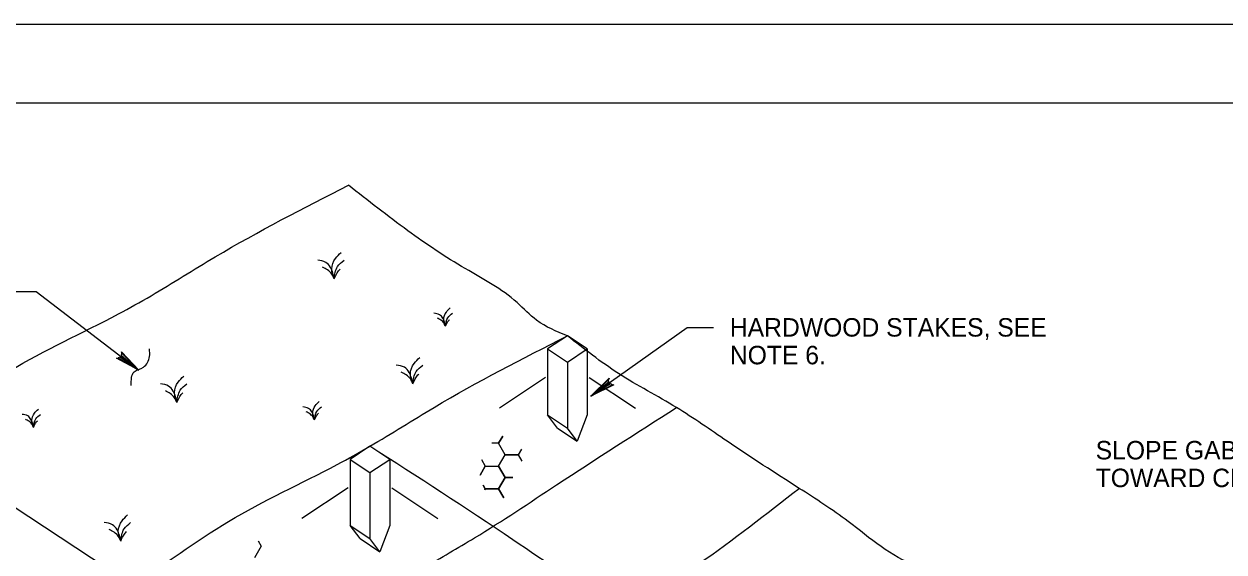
# Model space of a CAD drawing. Extents: x 3 to 3592, y -602 to 1171.
# Drawn here: x 3022.2 to 3249.7, y -107.8 to -7.8 of the extents above; entities that cross this region are included whole.
import ezdxf

# ---------------------------------------------------------------- set-up
doc = ezdxf.new("R2010")
doc.units = 0
for name, color, linetype in [('1', 7, 'Continuous'), ('2', 7, 'Continuous'), ('3', 7, 'Continuous')]:
    doc.layers.add(name, color=color, linetype=linetype)

msp = doc.modelspace()

# ---------------------------------------------------------------- linework, layer by layer
at = {"layer": '1'}
msp.add_lwpolyline([(2687.88, -7.81), (3528.88, -7.81), (3528.88, -601.81), (2687.88, -601.81)], close=True, dxfattribs=at)
msp.add_lwpolyline([(3512.88, -586.81), (3512.88, -22.81), (2726.88, -22.81), (2726.88, -586.81), (3512.88, -586.81), (3512.88, -560.45), (3312.88, -560.45), (3312.88, -495.77), (3512.88, -495.77), (3512.88, -466.81), (3312.88, -466.81), (3312.88, -586.81), (3391.68, -586.81), (3391.68, -560.45), (3391.68, -586.81), (3468.68, -586.81), (3468.68, -560.45), (3468.68, -572.77), (3512.88, -572.77)], dxfattribs=at)
at = {"layer": '2'}
for p, q in [((3121.47, -69.37), (3121.47, -81.87)), ((3128.97, -69.37), (3128.97, -81.87)), ((3128.97, -69.37), (3128.97, -69.37)), ((3125.22, -71.87), (3125.22, -84.37)), ((3121.08, -74.75), (3112.33, -80.58)), ((3128.97, -74.74), (3128.97, -74.74)), ((3129.36, -74.75), (3138.11, -80.58)), ((3121.47, -81.87), (3125.22, -84.37)), ((3123.35, -84.37), (3121.47, -81.87)), ((3128.97, -81.87), (3127.1, -86.87)), ((3123.35, -84.37), (3127.1, -86.87)), ((3127.1, -86.87), (3125.22, -84.37)), ((3084.03, -90.3), (3084.03, -102.8)), ((3091.53, -90.3), (3091.53, -102.8)), ((3091.53, -90.3), (3091.53, -90.3)), ((3041.32, -113.15), (3008.26, -91.4)), ((3087.78, -92.8), (3087.78, -105.3)), ((3083.64, -95.67), (3074.89, -101.51)), ((3091.53, -95.67), (3091.53, -95.67)), ((3091.92, -95.67), (3100.67, -101.51)), ((3084.03, -102.8), (3087.78, -105.3)), ((3085.91, -105.3), (3084.03, -102.8)), ((3091.53, -102.8), (3089.66, -107.8)), ((3085.91, -105.3), (3089.66, -107.8)), ((3089.66, -107.8), (3087.78, -105.3))]:
    msp.add_line(p, q, dxfattribs=at)
for points in [[(3019.53, -58.46), (3024.53, -58.46), (3043.97, -73.41)], [(3152.95, -65.36), (3147.95, -65.36), (3129.66, -78.3)], [(3040.72, -70.19), (3040.65, -70.55), (3043.97, -73.41), (3040.72, -70.19), (3040.66, -69.89), (3043.97, -73.41), (3040.38, -70.92), (3040.05, -71.08), (3043.97, -73.41), (3039.73, -71.1), (3040.05, -71.08)], [(3133.69, -76.14), (3133.37, -75.97), (3129.66, -78.3), (3133.69, -76.14), (3134, -76.17), (3129.66, -78.3), (3133.1, -75.6), (3133.04, -75.24), (3129.66, -78.3), (3133.12, -74.92), (3133.04, -75.24)], [(3112.95, -85.87), (3112.16, -87.23)], [(3112.16, -87.23), (3112.95, -85.87)], [(3112.16, -87.23), (3110.91, -87.23)], [(3113.41, -89.4), (3112.16, -87.23)], [(3116.52, -88.34), (3115.91, -89.4)], [(3108.94, -90.3), (3109.66, -91.56)], [(3112.16, -91.56), (3113.41, -89.4)], [(3113.41, -89.4), (3115.91, -89.4)], [(3115.91, -89.4), (3113.41, -89.4)], [(3115.91, -89.4), (3116.61, -90.6)], [(3109.66, -91.56), (3108.66, -93.3)], [(3108.66, -93.3), (3109.66, -91.56)], [(3109.66, -91.56), (3112.16, -91.56)], [(3112.16, -91.56), (3113.41, -93.73)], [(3113.41, -93.73), (3112.16, -91.56)], [(3109.24, -95.15), (3109.66, -95.89)], [(3109.66, -95.89), (3109.24, -95.15)], [(3113.41, -93.73), (3112.16, -95.89)], [(3112.16, -95.89), (3113.41, -93.73)], [(3113.41, -93.73), (3114.88, -93.73)], [(3114.88, -93.73), (3113.41, -93.73)], [(3109.66, -95.89), (3109.57, -96.05)], [(3109.57, -96.05), (3109.66, -95.89)], [(3109.66, -95.89), (3112.16, -95.89)], [(3112.16, -95.89), (3109.66, -95.89)], [(3112.16, -95.89), (3113.15, -97.59)], [(3113.15, -97.59), (3112.16, -95.89)], [(3067.17, -106.75), (3065.92, -108.92)], [(3066.57, -105.73), (3067.17, -106.75)]]:
    msp.add_lwpolyline(points, dxfattribs=at)
for points in [[(3125.22, -66.87), (3121.47, -69.37), (3125.22, -71.87), (3128.97, -69.37)], [(3087.78, -87.8), (3084.03, -90.3), (3087.78, -92.8), (3091.53, -90.3)]]:
    msp.add_lwpolyline(points, close=True, dxfattribs=at)
for points in [[(2952.58, -112.63), (2967.68, -103.18), (2983.97, -94.9), (2997.99, -87.4), (3001.19, -85.53), (3019.48, -73.54), (3040.11, -62.73), (3046.29, -59.28), (3058.46, -51.92), (3083.73, -38.35)], [(3125.22, -66.87), (3119.38, -63.94), (3115.7, -60.6), (3105.87, -54.16), (3094.97, -46.97), (3083.73, -38.35)], [(3080.99, -56.1), (3080.54, -54.21), (3081.24, -52.25), (3082.31, -51.11)], [(3080.99, -56.1), (3080.31, -53.93), (3079.42, -52.97), (3077.88, -52.57)], [(3080.99, -56.1), (3080.55, -55.18), (3079.74, -54.4), (3078.81, -53.88)], [(3080.99, -56.1), (3081.64, -53.78), (3082.88, -52.57)], [(3080.99, -56.1), (3081.83, -54.59), (3082.12, -54.26)], [(3102.09, -65.07), (3101.61, -63.56), (3100.99, -62.89), (3099.91, -62.61)], [(3102.09, -65.07), (3101.78, -64.43), (3101.21, -63.89), (3100.57, -63.53)], [(3102.09, -65.07), (3101.78, -63.76), (3102.27, -62.38), (3103.01, -61.59)], [(3102.09, -65.07), (3102.54, -63.45), (3103.42, -62.61)], [(3102.09, -65.07), (3102.68, -64.02), (3102.88, -63.79)], [(2994.89, -140.17), (3009.17, -131.7), (3025.46, -123.42), (3039.48, -115.92), (3042.68, -114.04), (3060.97, -102.06), (3081.6, -91.25), (3087.78, -87.8), (3099.95, -80.44), (3125.22, -66.87)], [(3217.42, -112.99), (3202.48, -111.68), (3191.36, -110.38), (3178.45, -102.06), (3169.16, -95.78), (3155.49, -86.84), (3145.91, -80.48), (3134.93, -74.03), (3125.22, -66.87)], [(3042.53, -76.28), (3043.11, -73.7), (3044.84, -72.83), (3045.99, -70.82), (3045.99, -69.38)], [(3095.9, -75.97), (3095.21, -73.81), (3094.33, -72.85), (3092.78, -72.45)], [(3095.9, -75.97), (3095.45, -74.09), (3096.15, -72.13), (3097.22, -70.99)], [(3095.9, -75.97), (3096.55, -73.66), (3097.79, -72.45)], [(3051.18, -79.52), (3050.73, -77.64), (3051.42, -75.68), (3052.49, -74.54)], [(3095.9, -75.97), (3095.46, -75.06), (3094.65, -74.28), (3093.72, -73.76)], [(3095.9, -75.97), (3096.74, -74.47), (3097.03, -74.14)], [(3051.18, -79.52), (3050.49, -77.35), (3049.6, -76.4), (3048.06, -76)], [(3051.18, -79.52), (3050.73, -78.61), (3049.92, -77.83), (3049, -77.31)], [(3051.18, -79.52), (3051.82, -77.21), (3053.07, -76)], [(3051.18, -79.52), (3052.01, -78.02), (3052.3, -77.69)], [(3077.25, -82.82), (3076.93, -81.5), (3077.42, -80.13), (3078.17, -79.34)], [(3024, -84.24), (3023.52, -82.72), (3022.9, -82.06), (3021.82, -81.78)], [(3024, -84.24), (3023.68, -82.92), (3024.17, -81.55), (3024.92, -80.76)], [(3024, -84.24), (3024.45, -82.62), (3025.32, -81.78)], [(3024.13, -159.41), (3038.81, -150.12), (3053.49, -141.05), (3067.11, -132.41), (3081.26, -122.62), (3098.08, -110.87), (3107.61, -105.16), (3123.18, -95.12), (3145.91, -80.48)], [(3077.25, -82.82), (3076.76, -81.3), (3076.15, -80.64), (3075.06, -80.36)], [(3077.25, -82.82), (3076.93, -82.18), (3076.36, -81.64), (3075.72, -81.28)], [(3077.25, -82.82), (3077.7, -81.2), (3078.57, -80.36)], [(3077.25, -82.82), (3077.83, -81.77), (3078.03, -81.54)], [(3024, -84.24), (3023.69, -83.6), (3023.12, -83.06), (3022.47, -82.7)], [(3024, -84.24), (3024.58, -83.19), (3024.79, -82.96)], [(3189.54, -138.32), (3174.44, -136.51), (3160.11, -135.38), (3145.08, -125.29), (3133.86, -118.08), (3114.9, -105.53), (3087.78, -87.8)], [(3053.37, -178.64), (3070.85, -165.88), (3095.07, -149.7), (3108.76, -138.91), (3134.27, -120.61), (3150.15, -110.07), (3169.16, -95.78)], [(3040.53, -105.79), (3039.84, -103.62), (3038.95, -102.67), (3037.41, -102.27)], [(3040.53, -105.79), (3040.08, -103.91), (3040.78, -101.95), (3041.84, -100.81)], [(3040.53, -105.79), (3041.17, -103.48), (3042.42, -102.27)], [(3040.53, -105.79), (3040.08, -104.87), (3039.27, -104.1), (3038.35, -103.58)], [(3040.53, -105.79), (3041.36, -104.28), (3041.65, -103.96)]]:
    msp.add_spline(points, degree=3, dxfattribs=at)

# ---------------------------------------------------------------- texts
at = {"layer": '3'}
for s, p in [('HARDWOOD STAKES, SEE', (3156.02, -67.03)), ('NOTE 6.', (3156.02, -72.28)), ('SLOPE GABIONS', (3225.38, -90.3)), ('TOWARD CHANNEL', (3225.38, -95.55))]:
    msp.add_text(s, height=3.5, dxfattribs=at).set_placement(p)

doc.saveas('drawing.dxf')
